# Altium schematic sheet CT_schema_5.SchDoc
size 208 x 258 mm
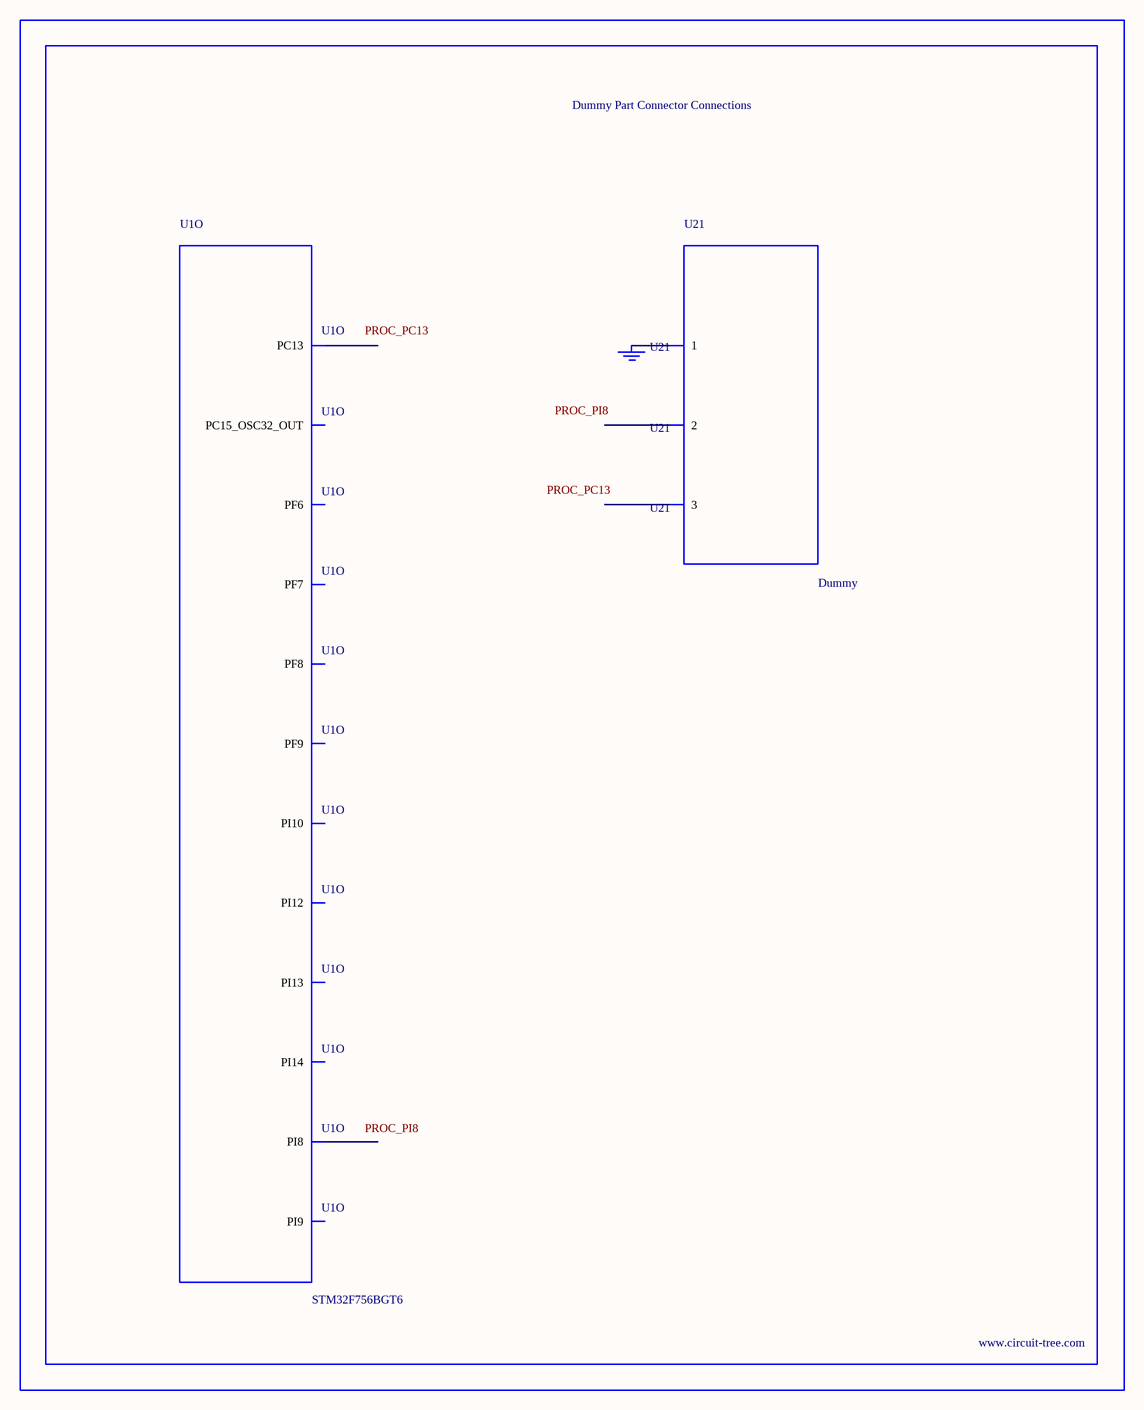
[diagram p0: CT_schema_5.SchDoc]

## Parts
BORDER4  (no value)
GND_INSTANCE_4_0  (no value)
U1  STM32F756BGT6  [LQFP208]  (part O of 15)
U21  Dummy  [DUMMY_PACKAGE_239]

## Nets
NetGND_INSTANCE_4_0_0: GND_INSTANCE_4_0.0(GND) U21.1

Not connected (* = marked no-connect by the designer): U1 7(PI8) 8(PC13) 10(PC15_OSC32_OUT) 11(PI9) 12(PI10) 19(PI12) 20(PI13) 21(PI14) 27(PF6) 28(PF7) 29(PF8) 30(PF9); U21 2 3

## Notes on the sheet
- Labels drawn without touching a wire or pin: PROC_PC13, PROC_PI8

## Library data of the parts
BORDER4 = BORDER_PAGE4
GND_INSTANCE_4_0 = GND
